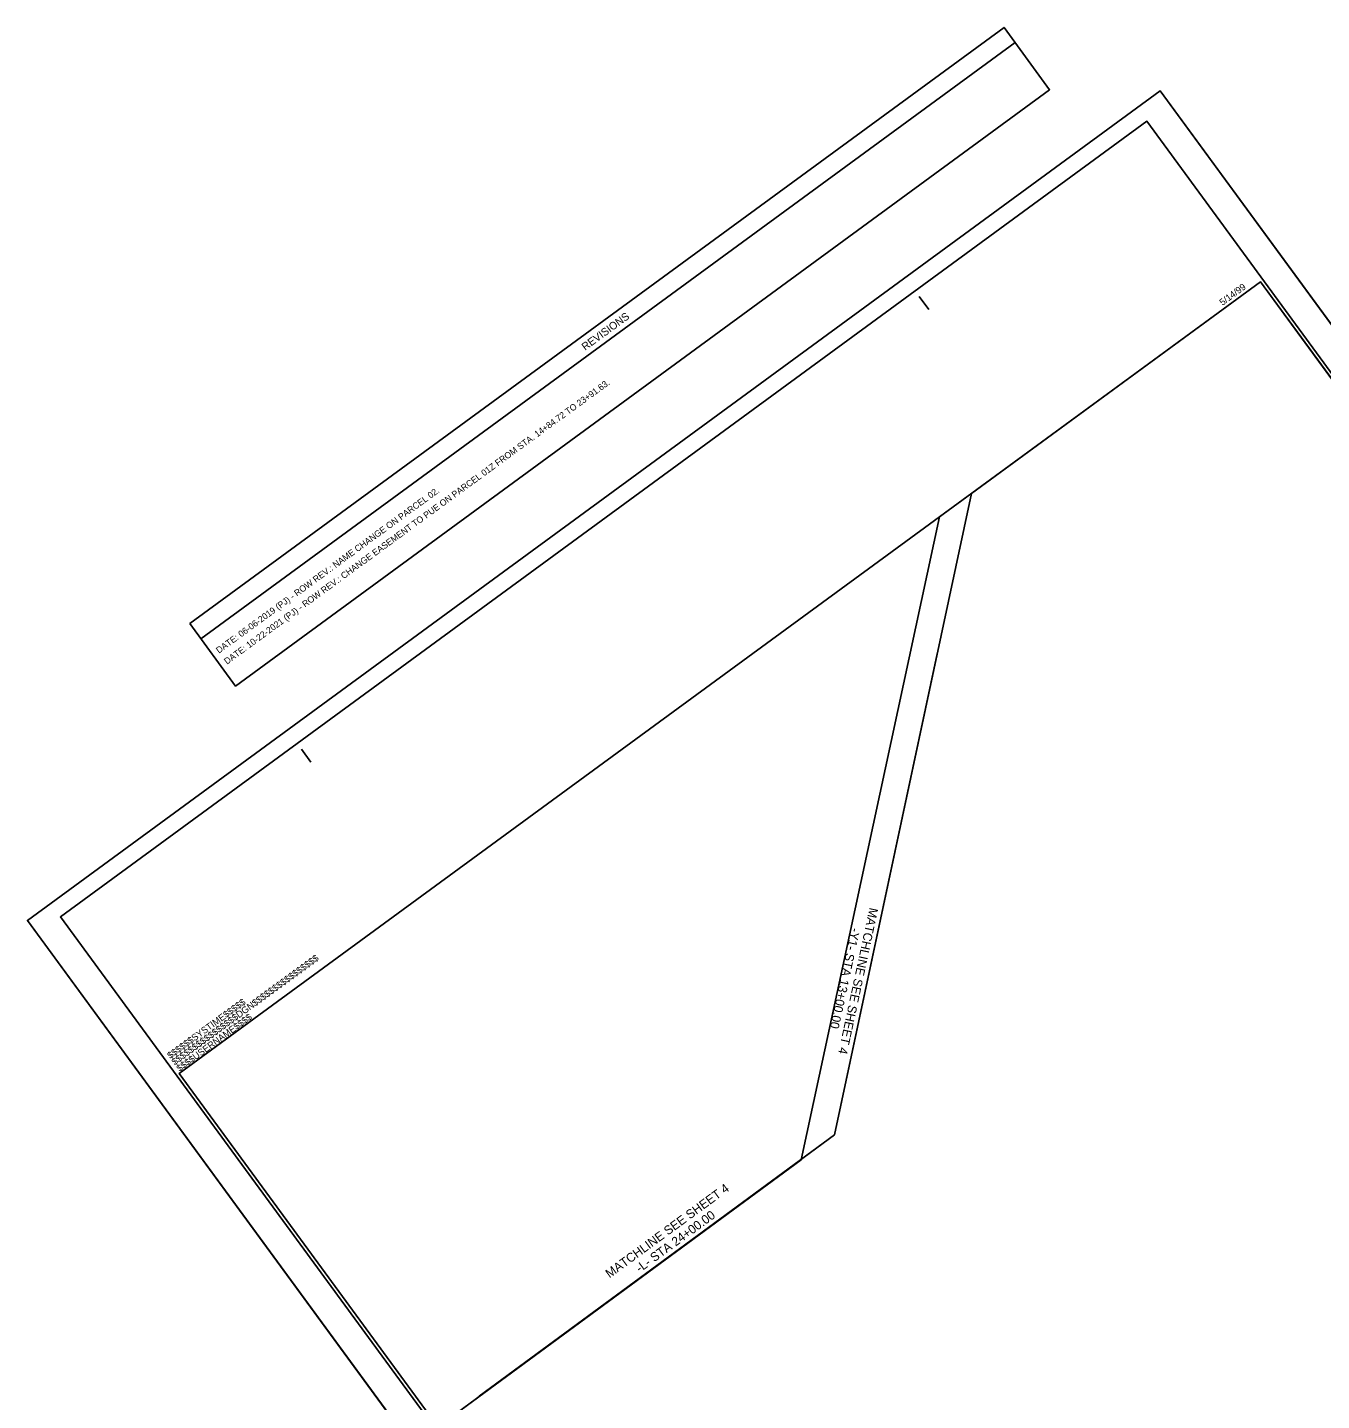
# Model space of a CAD drawing. Extents: x 1762935 to 1764817, y 711157 to 713215.
# Drawn here: x 1762935 to 1763949, y 712140 to 713215 of the extents above; entities that cross this region are included whole.
import ezdxf

# ---------------------------------------------------------------- set-up
doc = ezdxf.new("R2010")
doc.units = 0
for name, color, linetype in [('Default', 7, 'Continuous'), ('Matchline', 7, 'Continuous'), ('Matchline Text', 7, 'Continuous'), ('Scratch_Level_3', 7, 'Continuous'), ('Sheet Block Revision CELL', 7, 'Continuous'), ('Sheet Border Standard 30in CELL', 7, 'Continuous'), ('Sheet Cutting Line CELL', 7, 'Continuous'), ('Sheet Plot Border Inside CELL', 7, 'Continuous'), ('Sheet Plot Border Outside CELL', 7, 'Continuous')]:
    doc.layers.add(name, color=color, linetype=linetype)

msp = doc.modelspace()

# ---------------------------------------------------------------- linework, layer by layer
at = {"layer": 'Default'}
msp.add_lwpolyline([(1763819.3, 711353.7), (1763256.7, 712119.2), (1763541, 712328.2), (1763649.3, 712832), (1763900.7, 713016.1), (1764665.3, 711975.5), (1764374.6, 711761.8)], close=True, dxfattribs=at)
at = {"layer": 'Matchline'}
for p, q in [((1763567.1, 712347.6), (1763647.5, 712724.5)), ((1763288.7, 712142.9), (1763567.1, 712347.6))]:
    msp.add_line(p, q, dxfattribs=at)
at = {"layer": 'Scratch_Level_3'}
for p, q in [((1763674.3, 712850.2), (1763900.7, 713016.1)), ((1763674.3, 712850.2), (1763900.7, 713016.1)), ((1763567.1, 712347.6), (1763674.3, 712850.2)), ((1763567.1, 712347.6), (1763674.3, 712850.2)), ((1763256.7, 712119.2), (1763567.1, 712347.6)), ((1763256.7, 712119.2), (1763567.1, 712347.6))]:
    msp.add_line(p, q, dxfattribs=at)
for points in [[(1763900.7, 713016.1), (1764563.7, 712110.9), (1764544.2, 712136.2)], [(1763900.7, 713016.1), (1764563.7, 712110.9), (1764557, 712118.7)]]:
    msp.add_lwpolyline(points, dxfattribs=at)
at = {"layer": 'Sheet Block Revision CELL'}
msp.add_line((1763070.6, 712736.4), (1763708.5, 713203.6), dxfattribs=at)
msp.add_lwpolyline([(1763062, 712748.2), (1763699.9, 713215.3), (1763735.6, 713166.5), (1763097.8, 712699.3)], close=True, dxfattribs=at)
at = {"layer": 'Sheet Border Standard 30in CELL'}
for p, q in [((1763901.3, 713015.3), (1763901.3, 713015.3)), ((1763633.5, 713004.4), (1763640.9, 712994.3)), ((1763149.4, 712649.9), (1763156.8, 712639.8))]:
    msp.add_line(p, q, dxfattribs=at)
msp.add_lwpolyline([(1764787, 711805.9), (1763900.7, 713016.1), (1763053.6, 712395.7), (1763939.9, 711185.5)], close=True, dxfattribs=at)
at = {"layer": 'Sheet Cutting Line CELL'}
for p, q in [((1763822.2, 713165.6), (1762934.8, 712515.7)), ((1764817.2, 711807), (1763822.2, 713165.6)), ((1762934.8, 712515.7), (1763929.8, 711157))]:
    msp.add_line(p, q, dxfattribs=at)
at = {"layer": 'Sheet Plot Border Inside CELL'}
msp.add_lwpolyline([(1764796.5, 711797.3), (1763811.8, 713141.8), (1762960.6, 712518.4), (1763945.2, 711173.9)], close=True, dxfattribs=at)
at = {"layer": 'Sheet Plot Border Outside CELL'}
msp.add_lwpolyline([(1764817.2, 711807), (1763822.2, 713165.6), (1762934.8, 712515.7), (1763929.8, 711157)], close=True, dxfattribs=at)

# ---------------------------------------------------------------- texts
at = {"layer": 'Matchline Text'}
for s, rotation, p in [('MATCHLINE SEE SHEET 4 ', 257.8638, (1763594.5, 712526.1)), ('-Y1- STA 13+00.00', 257.8638, (1763580.3, 712510.3)), ('MATCHLINE SEE SHEET 4 ', 36.2176, (1763390.8, 712235.2)), ('-L- STA 24+00.00', 36.2176, (1763414.5, 712239.5))]:
    msp.add_text(s, height=7, rotation=rotation, dxfattribs=at).set_placement(p)
at = {"layer": 'Sheet Block Revision CELL'}
for s, height, p in [('REVISIONS', 6, (1763371.7, 712961.9)), ('DATE: 10-22-2021 (PJ) - ROW REV.: CHANGE EASEMENT TO PUE ON PARCEL 01Z FROM STA. 14+84.72 TO 23+91.63.', 5, (1763091.1, 712716)), ('DATE: 06-06-2019 (PJ) - ROW REV.: NAME CHANGE ON PARCEL 02.', 5, (1763084.8, 712724.6))]:
    msp.add_text(s, height=height, rotation=36.2176, dxfattribs=at).set_placement(p)
at = {"layer": 'Sheet Border Standard 30in CELL'}
for s, p in [('5/14/99', (1763871, 712997.1)), ('$$$$$$$$$$$$$$$$DGN$$$$$$$$$$$$$$$$', (1763050.1, 712402)), ('$$$$$$SYSTIME$$$$$', (1763046.7, 712407)), ('$$$$USERNAME$$$$', (1763053.9, 712396.9))]:
    msp.add_text(s, height=5.25, rotation=36.2176, dxfattribs=at).set_placement(p)

doc.saveas('drawing.dxf')
